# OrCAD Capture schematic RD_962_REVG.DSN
size B
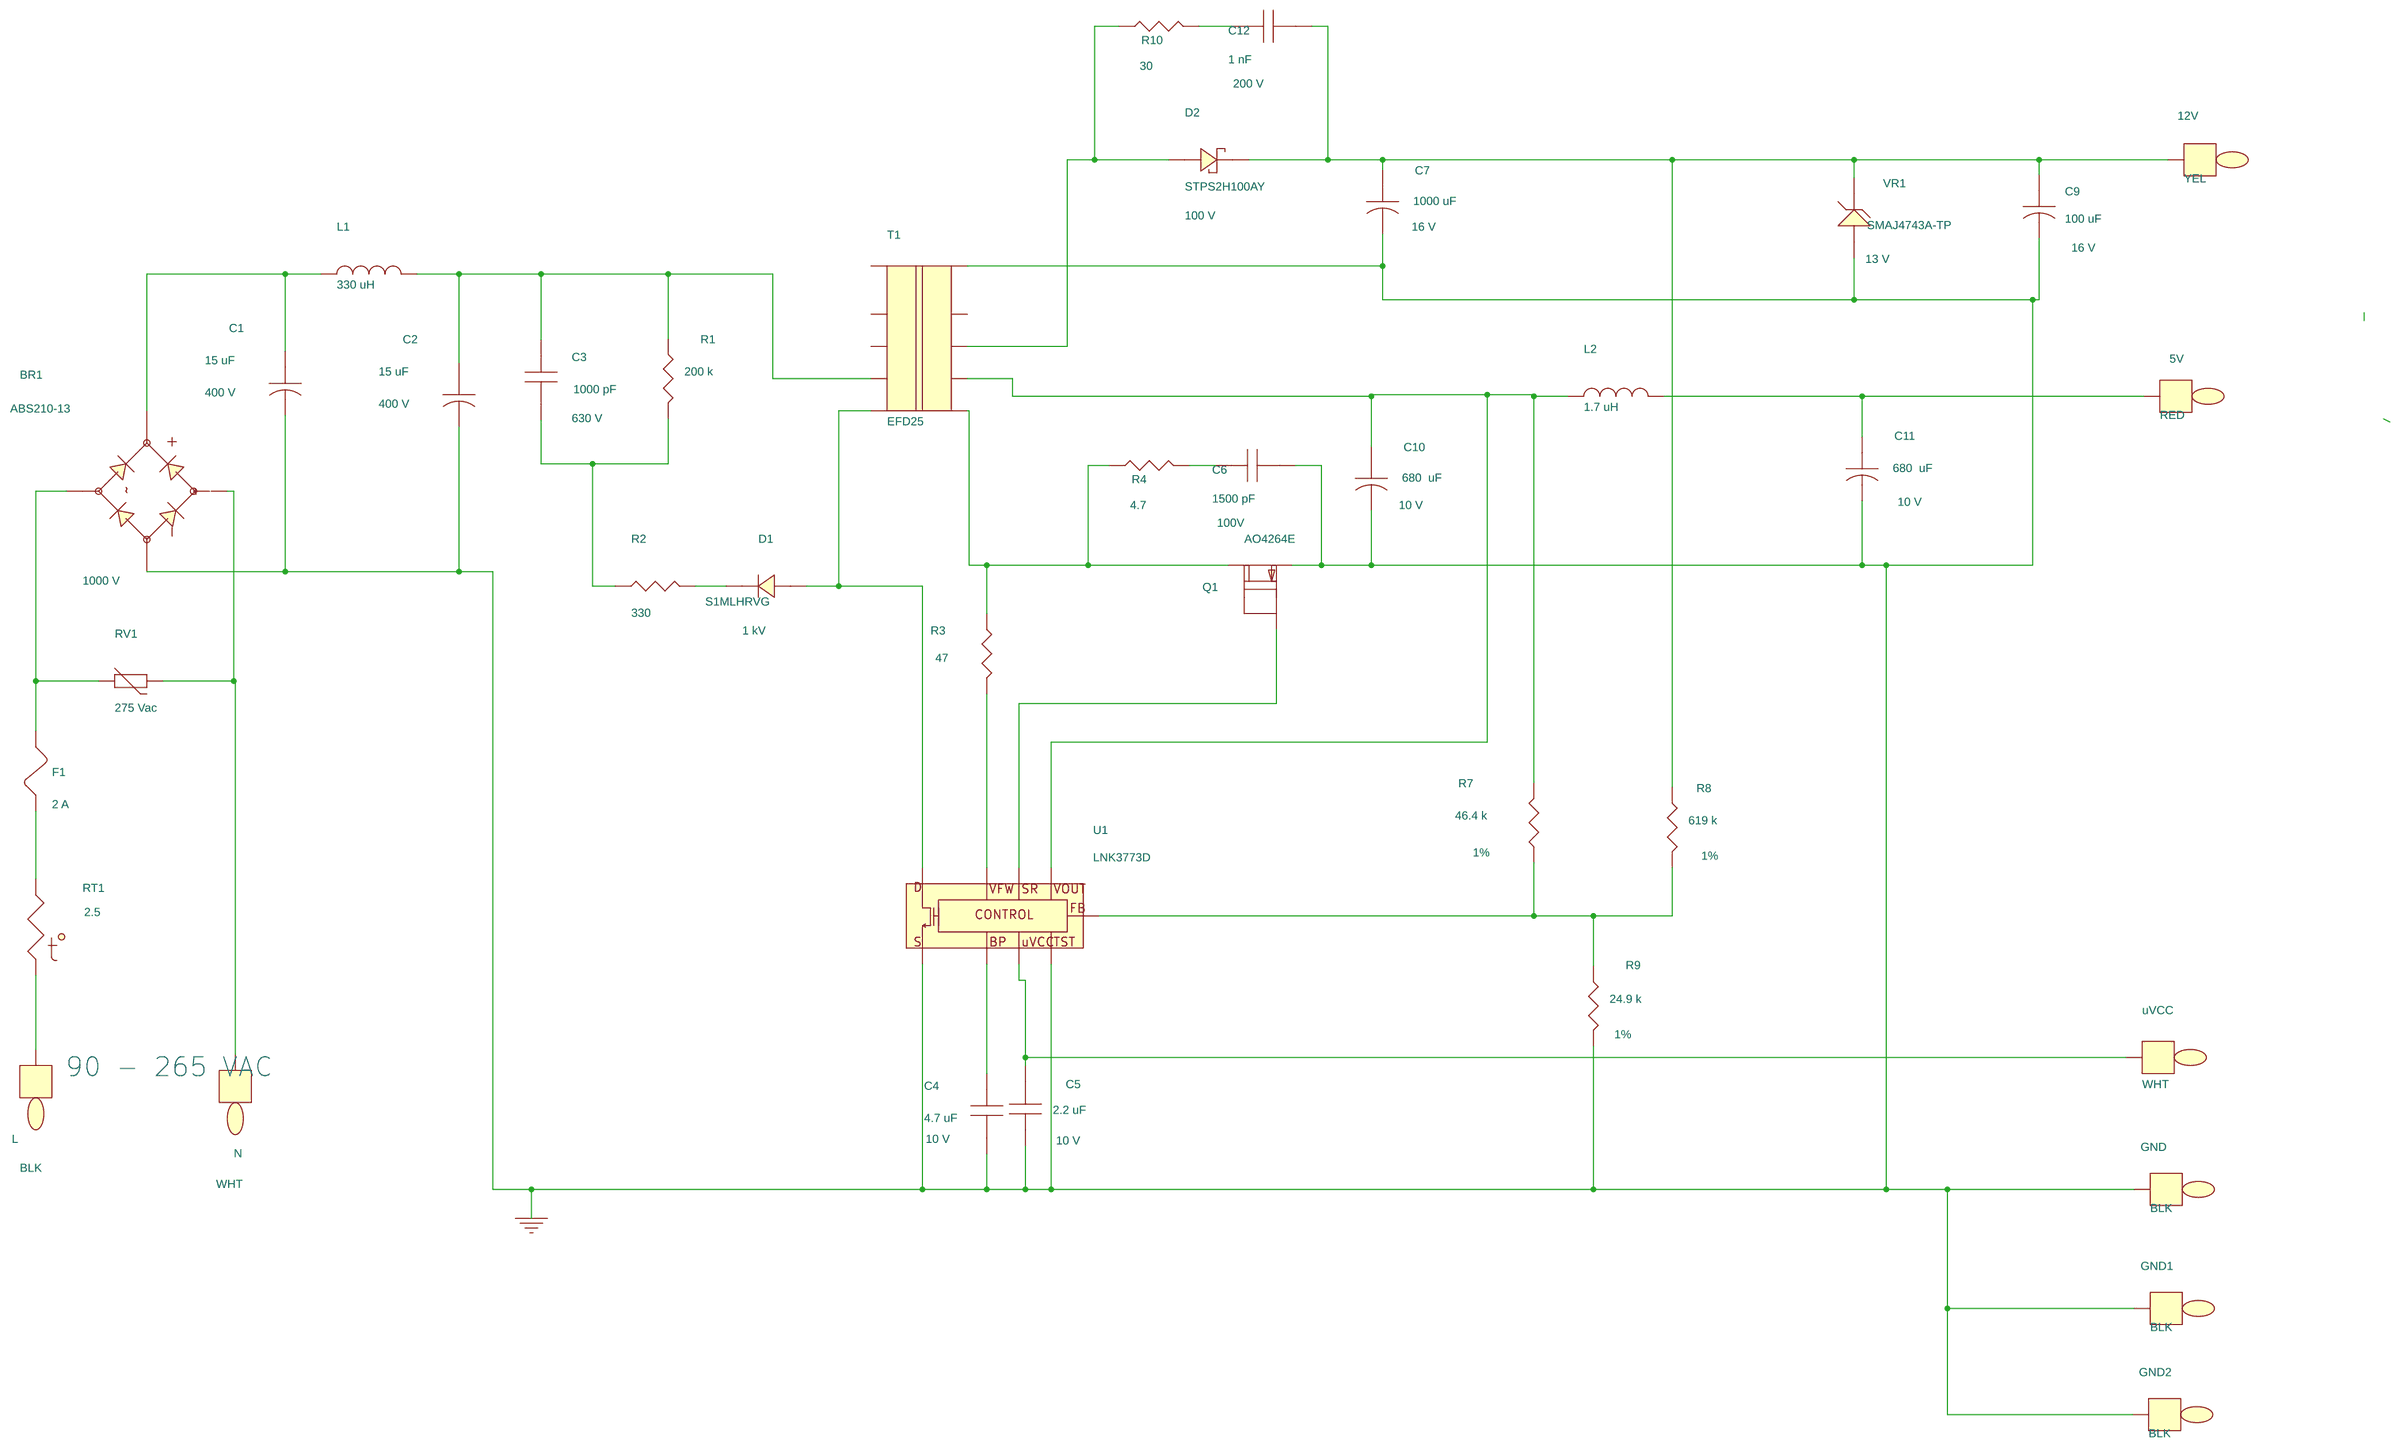
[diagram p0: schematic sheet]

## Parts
5V  RED  [pitpkeystone100x100]
12V  YEL  [pitpkeystone100x100]
BR1  ABS210-13  [pismd_SOPA-4]
C1  15 uF  [pipolcapcyld400ls200040]
C2  15 uF  [pipolcapcyld400ls200040]
C3  1000 pF  [pismc1206]
C4  4.7 uF  [pismc0805]
C5  2.2 uF  [pismc0805]
C6  1500 pF  [pismc0805]
C7  1000 uF  [pipolcapclyd320ls140030]
C9  100 uF  [pipolcapcyld250ls100030]
C10  680  uF  [pipolcapclyd320ls140030]
C11  680  uF  [pipolcapclyd320ls140030]
C12  1 nF  [pismc0805]
D1  S1MLHRVG  [pi_sm_sod-123_12]
D2  STPS2H100AY  [pismdsma]
F1  2 A  [pi_rst_microfuse]
GND  BLK  [pitpkeystone100x100]
GND1  BLK  [pitpkeystone100x100]
GND2  BLK  [pitpkeystone100x100]
L  BLK  [pitpkeystone100x100]
L1  330 uH  [pichoketokinvd345h453ls197d030]
L2  1.7 uH  [pichoke6mm2pin4mmLSd030]
N  WHT  [pitpkeystone100x100]
Q1  AO4264E  [pismso8]
R1  200 k  [pismr1206]
R2  330  [pismr1206]
R3  47  [pismr1206]
R4  4.7  [pismr0805]
R7  46.4 k  [pismr0603]
R8  619 k  [pismr0603]
R9  24.9 k  [pismr0603]
R10  30  [pismr0805]
RT1  2.5  [pi_rad150x300ls200d030]
RV1  275 Vac  [pi_disc_475x200ls295x90d040]
T1  EFD25  [pi_bobbin_efd25_10p]
U1  LNK3773D  [pi_smd_so_14-16p_short9-14]
uVCC  WHT  [pitpkeystone100x100]
VR1  SMAJ4743A-TP  [pismdo214ac12]

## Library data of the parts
5V = TESTPOINT: Part Number: 35-00080-00
12V = TESTPOINT: Part Number: 35-00404-00
BR1 = DIODE_BRIDGE_+~~-: ALT_SYMBOLS: pismd_SOPA-4a,pi_sm_soic4_slot; Disp_Voltage: 1000 V; FPLIST: pismd_SOPA-4,pismd_SOPA-4a,pi_sm_soic4_slot; Part Number: 15-01254-00
C1 C2 = CAP_POL: ALT_SYMBOLS: pipolcapclyd400x630ls200030h; Disp_Voltage: 400 V; FPLIST: pipolcapcyld400ls200040,pipolcapclyd400x630ls200030h; Part Number: 20-08745-00; Voltage: 400 V
C3 = CAP_NP: Disp_Voltage: 630 V; Part Number: 20-08616-00; Voltage: 630 V
C4 = CAP_NP: Disp_Voltage: 10 V; Part Number: 20-01487-00; Voltage: 10 V
C5 = CAP_NP: Disp_Voltage: 10 V; Part Number: 20-08747-00; Voltage: 10 V
C6 = CAP_NP: ALT_SYMBOLS: CC0805; Disp_Voltage: 100V; FPLIST: pismc0805,CC0805; Part Number: 20-02002-00; Voltage: 100V
C7 = CAP_POL: ALT_SYMBOLS: pipolcapclyd320ls140d30h750; Disp_Voltage: 16 V; FPLIST: pipolcapclyd320ls140030,pipolcapclyd320ls140d30h750; Part Number: 20-08710-00; Voltage: 16 V
C9 = CAP_POL: ALT_SYMBOLS: pipolcapcyld250ls100030h; Disp_Voltage: 16 V; FPLIST: pipolcapcyld250ls100030,pipolcapcyld250ls100030h; Part Number: 20-00079-00; Voltage: 16 V
C10 C11 = CAP_POL: Disp_Voltage: 10 V; FPLIST: pipolcapclyd320ls140030,pipolcapclyd320ls140030430h; Part Number: 20-00004-00; Voltage: 10 V
C12 = CAP_NP: ALT_SYMBOLS: pismc0805_1; Disp_Voltage: 200 V; FPLIST: pismc0805,pismc0805_1; Part Number: 20-00737-00; Voltage: 200 V
D1 = DIODE: Disp_Voltage: 1 kV; Part Number: 15-01663-00
D2 = DIODE_SCHOTTKY: Disp_Voltage: 100 V; Part Number: 15-00985-00
F1 = FUSE: ALT_SYMBOLS: pirstmicrofusehoz; FPLIST: pi_rst_microfuse,pirstmicrofusehoz; Part Number: 40-00021-00
GND GND1 GND2 = TESTPOINT: Part Number: 35-00079-00
L = TESTPOINT: ALT_SYMBOLS: TP_TH_CR2_D1_1; FPLIST: pitpkeystone100x100,TP_TH_CR2_D1_1; Part Number: 35-00079-00
L1 = INDUCTOR: ALT_SYMBOLS: pichoketokinvd345h453ls197d030H; Part Number: 30-00077-00
L2 = INDUCTOR: Part Number: 30-00451-00
N uVCC = TESTPOINT: Part Number: 35-00081-00
Q1 = FET_P_SGD_123_4_5678: Part Number: 50-00368-00
R1 = R: Part Number: 05-01407-00
R2 = R: Part Number: 05-01340-00
R3 = R: Part Number: 05-01320-00
R4 = R: Part Number: 05-01463-00
R7 = R: Disp_Tol: 1%; Part Number: 05-03248-00
R8 = R: Disp_Tol: 1%; Part Number: 05-01250-00
R9 = R: Disp_Tol: 1%; Part Number: 05-03222-00
R10 = R: Part Number: 05-01482-00
RT1 = THERMISTOR: ALT_SYMBOLS: pirad400x300ls200040_h; FPLIST: pi_rad150x300ls200d030,pirad400x300ls200040_h; Part Number: 90-00040-00
RV1 = VARISTOR: Part Number: 85-00022-00
T1 = BEFD25_10P_GENERIC: Part Number: 25-00017-00
U1 = LNKXT2-SR2: Part Number: 10-01361-00
VR1 = DIODE_ZENER: Disp_Voltage: 13 V; Part Number: 15-01862-00

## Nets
0: BR1.4 C1.2 C2.2 C4.2 C5.1 C6.2 C7.2 C9.2 C10.2 C11.2 GND.1 GND1.1 GND2.1 Q1.1(S) R9.2 T1.10 U1.5 U1.9 VR1.2
N11170642: C2.1 C3.1 L1.2 R1.1 T1.4
N11170782: BR1.1 C1.1 L1.1
N11170894: 5V.1 C11.1 L2.2
N11170962: C3.2 R1.2 R2.1
N11171108: Q1.5(D) R3.2 R4.1 T1.6
N11171534: R3.1 U1.4
N11182138: Q1.4(G) U1.3
N11187578: 12V.1 C7.1 C9.1 C12.2 D2.1 R8.1 VR1.1
N11188222: C5.2 U1.15 uVCC.1
N11194985: BR1.2 N.1 RV1.2
N11194992: BR1.3 F1.2 RV1.1
N11203470: F1.1 RT1.1
N11204081: R7.2 R8.2 R9.1 U1.1
N11210341: D2.2 R10.1 T1.8
N11218878: C10.1 L2.1 R7.1 T1.7 U1.2
N11259707: C6.1 R4.2
N11261351: D1.2 T1.5 U1.8
N11265143: C4.1 U1.16
N11281825: D1.1 R2.2
N11293270: L.1 RT1.2
N11294619: C12.1 R10.2

Not connected (* = marked no-connect by the designer): Q1 2(S2) 3(S3) 6(D6) 7(D7) 8(D8); T1 1 2 3 9; U1 10 11 12 13 14

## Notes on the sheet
- 90 - 265 VAC
